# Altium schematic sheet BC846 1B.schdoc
size 127 x 101 mm
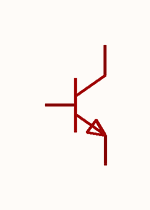
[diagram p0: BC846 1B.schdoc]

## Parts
Q?  bc846b(range:200-450)  [SOT-23-3_L2.9-W1.6-P1.90-LS2.8-BR]  (value not drawn)

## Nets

Not connected (* = marked no-connect by the designer): Q? 1(B) 2(E) 3(C)

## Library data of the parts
Q? = bc846b(range:200-450): 晶体管类型:NPN;集电极电流(Ic):100mA;集射极击穿电压(Vceo):65V;耗散功率(Pd):200mW;直流电流增益(hFE):200;; Manufacturer: CJ(江苏长电/长晶); Symbol: BC846 1B; AddInBom: yes; ModelId: 89cb27a44ab2466697082bb9fd73a7d0; ModelName: SOT-23-3L_L2.9-W1.6-H1.1-LS2.8-P0.95; ModelTransform: 114.173,110.236,0,90,0,0,0,0,0; type: NPN; Current - Collector(Ic): 100mA; Collector - Emitter Voltage VCEO: 65V; Pd - Power Dissipation: 200mW; DC Current Gain: 200; Transition frequency(fT): 100MHz; Current - Collector Cutoff: 100nA; Vce Saturation(VCE(sat)): 500mV; Emitter-Base Voltage(Vebo): 6V; Number: 1个NPN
